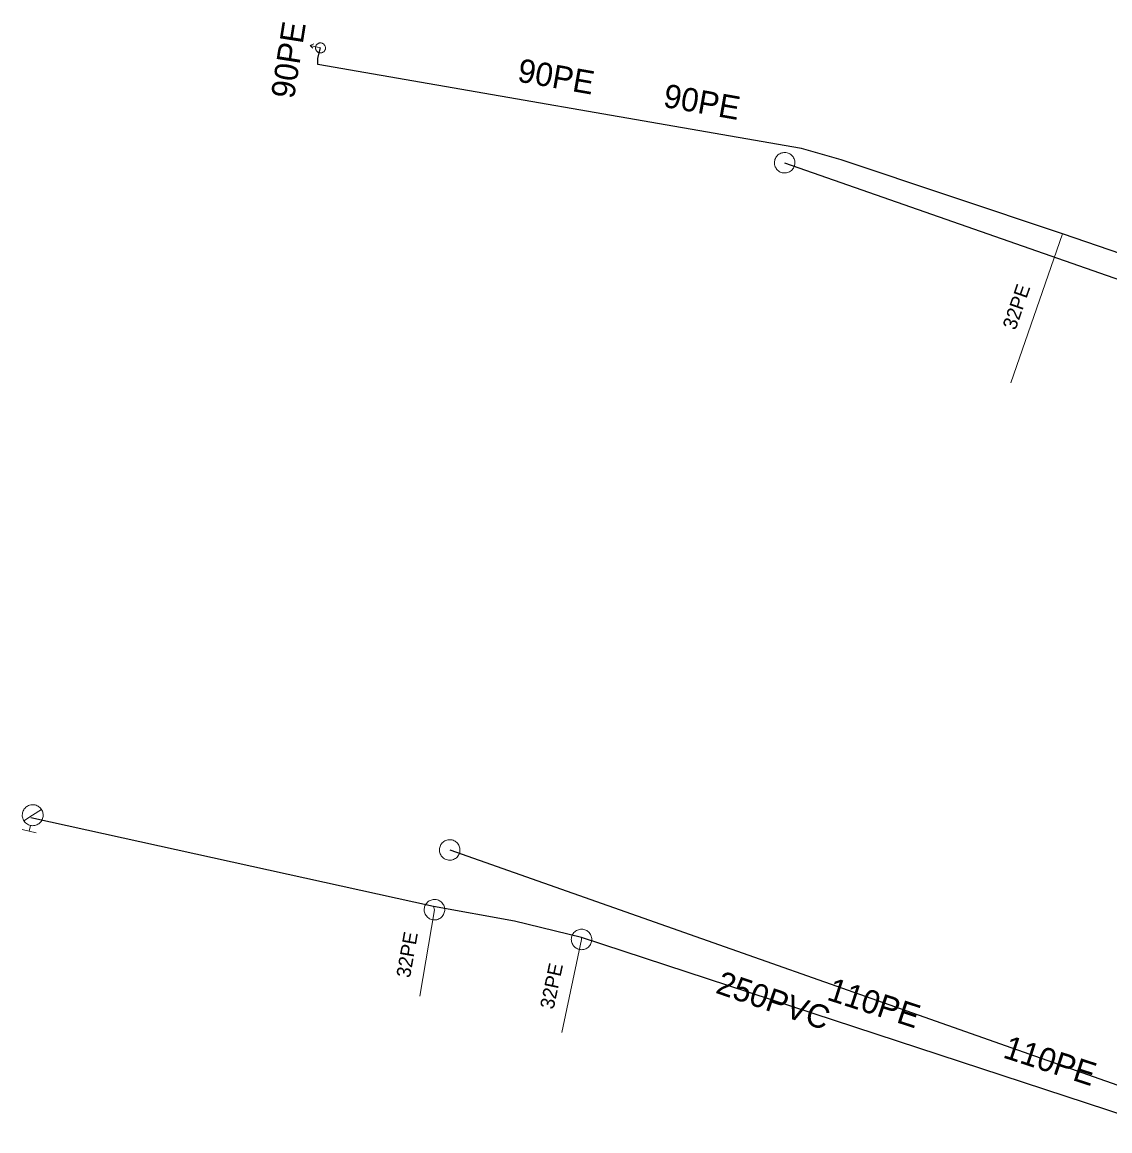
# Model space of a CAD drawing. Extents: x -741806 to -738704, y -1059275 to -1055387.
# Drawn here: x -740744.78 to -740698.33, y -1058174.38 to -1058127.05 of the extents above; entities that cross this region are included whole.
import ezdxf

# ---------------------------------------------------------------- set-up
doc = ezdxf.new("R2010")
doc.units = 0
doc.header["$LTSCALE"] = 0.4
for name, color, linetype, lineweight in [('2', 7, 'Continuous', 25), ('21', 7, 'Continuous', 13), ('3', 7, 'Continuous', 13), ('36', 7, 'Continuous', 13), ('50', 7, 'Continuous', 13), ('51', 7, 'Continuous', 13), ('52', 7, 'Continuous', 25)]:
    doc.layers.add(name, color=color, linetype=linetype, lineweight=lineweight)
for name, color, linetype in [('5', 7, 'Continuous'), ('53', 7, 'Continuous'), ('54', 7, 'Continuous')]:
    doc.layers.add(name, color=color, linetype=linetype)

msp = doc.modelspace()

# ---------------------------------------------------------------- linework, layer by layer
at = {"layer": '2'}
for p, q in [((-740712.219, -1058133.05), (-740673.62, -1058146.55)), ((-740726.52, -1058162.389), (-740696.93, -1058172.81))]:
    msp.add_line(p, q, dxfattribs=at)
at = {"layer": '21'}
msp.add_line((-740700.35, -1058136.09), (-740702.561, -1058142.45), dxfattribs=at)
for points in [[(-740727.219, -1058164.8), (-740727.17, -1058164.94), (-740727.796, -1058168.629)], [(-740720.899, -1058166.12), (-740720.89, -1058166.21), (-740721.732, -1058170.186)]]:
    msp.add_lwpolyline(points, dxfattribs=at)
at = {"layer": '3'}
for points in [[(-740711.805, -1058133.195), (-740711.793, -1058133.151), (-740711.785, -1058133.106), (-740711.781, -1058133.06), (-740711.783, -1058133.015), (-740711.789, -1058132.969), (-740711.8, -1058132.924), (-740711.815, -1058132.882), (-740711.835, -1058132.84), (-740711.86, -1058132.802), (-740711.887, -1058132.765), (-740711.919, -1058132.732), (-740711.954, -1058132.702), (-740711.992, -1058132.677), (-740712.032, -1058132.655), (-740712.074, -1058132.637), (-740712.118, -1058132.624), (-740712.164, -1058132.617), (-740712.209, -1058132.613), (-740712.255, -1058132.615), (-740712.301, -1058132.621), (-740712.345, -1058132.632), (-740712.387, -1058132.647), (-740712.429, -1058132.667), (-740712.468, -1058132.691), (-740712.504, -1058132.719), (-740712.537, -1058132.751), (-740712.567, -1058132.785), (-740712.593, -1058132.824), (-740712.614, -1058132.864), (-740712.631, -1058132.907), (-740712.644, -1058132.95), (-740712.653, -1058132.995), (-740712.656, -1058133.041), (-740712.654, -1058133.087), (-740712.649, -1058133.132), (-740712.638, -1058133.177), (-740712.622, -1058133.219), (-740712.602, -1058133.261), (-740712.578, -1058133.299), (-740712.551, -1058133.335), (-740712.519, -1058133.369), (-740712.484, -1058133.399), (-740712.446, -1058133.425), (-740712.406, -1058133.446), (-740712.363, -1058133.463), (-740712.319, -1058133.477), (-740712.274, -1058133.485), (-740712.229, -1058133.488), (-740712.183, -1058133.486), (-740712.137, -1058133.48), (-740712.093, -1058133.469), (-740712.05, -1058133.454), (-740712.009, -1058133.434), (-740711.97, -1058133.41), (-740711.933, -1058133.382), (-740711.9, -1058133.35), (-740711.871, -1058133.316), (-740711.845, -1058133.277), (-740711.823, -1058133.237), (-740711.806, -1058133.196)], [(-740726.107, -1058162.534), (-740726.094, -1058162.491), (-740726.086, -1058162.446), (-740726.082, -1058162.4), (-740726.084, -1058162.355), (-740726.09, -1058162.309), (-740726.1, -1058162.264), (-740726.116, -1058162.221), (-740726.135, -1058162.18), (-740726.16, -1058162.141), (-740726.188, -1058162.105), (-740726.219, -1058162.072), (-740726.254, -1058162.041), (-740726.292, -1058162.016), (-740726.332, -1058161.994), (-740726.375, -1058161.977), (-740726.419, -1058161.963), (-740726.464, -1058161.956), (-740726.509, -1058161.952), (-740726.555, -1058161.954), (-740726.601, -1058161.96), (-740726.645, -1058161.971), (-740726.687, -1058161.985), (-740726.729, -1058162.006), (-740726.768, -1058162.029), (-740726.805, -1058162.057), (-740726.837, -1058162.089), (-740726.867, -1058162.123), (-740726.893, -1058162.162), (-740726.915, -1058162.202), (-740726.932, -1058162.245), (-740726.945, -1058162.288), (-740726.954, -1058162.333), (-740726.957, -1058162.379), (-740726.955, -1058162.425), (-740726.95, -1058162.47), (-740726.939, -1058162.515), (-740726.924, -1058162.557), (-740726.903, -1058162.599), (-740726.88, -1058162.638), (-740726.852, -1058162.674), (-740726.82, -1058162.707), (-740726.786, -1058162.737), (-740726.748, -1058162.763), (-740726.708, -1058162.785), (-740726.665, -1058162.802), (-740726.621, -1058162.815), (-740726.576, -1058162.824), (-740726.531, -1058162.827), (-740726.485, -1058162.825), (-740726.439, -1058162.819), (-740726.395, -1058162.808), (-740726.352, -1058162.794), (-740726.31, -1058162.773), (-740726.271, -1058162.75), (-740726.235, -1058162.721), (-740726.201, -1058162.69), (-740726.172, -1058162.655), (-740726.146, -1058162.617), (-740726.125, -1058162.577), (-740726.107, -1058162.535)]]:
    msp.add_lwpolyline(points, dxfattribs=at)
at = {"layer": '36'}
msp.add_line((-740732.473, -1058128.04), (-740732.321, -1058127.978), dxfattribs=at)
msp.add_lwpolyline([(-740732.038, -1058128.149), (-740732.473, -1058128.04), (-740732.368, -1058128.166)], dxfattribs=at)
msp.add_lwpolyline([(-740731.986, -1058127.942), (-740732.009, -1058127.937), (-740732.03, -1058127.935), (-740732.053, -1058127.936), (-740732.075, -1058127.938), (-740732.097, -1058127.943), (-740732.117, -1058127.95), (-740732.138, -1058127.96), (-740732.158, -1058127.971), (-740732.176, -1058127.985), (-740732.192, -1058128), (-740732.206, -1058128.017), (-740732.219, -1058128.035), (-740732.23, -1058128.054), (-740732.238, -1058128.075), (-740732.245, -1058128.097), (-740732.249, -1058128.119), (-740732.251, -1058128.141), (-740732.251, -1058128.163), (-740732.248, -1058128.185), (-740732.243, -1058128.207), (-740732.236, -1058128.228), (-740732.227, -1058128.248), (-740732.215, -1058128.267), (-740732.201, -1058128.285), (-740732.186, -1058128.301), (-740732.169, -1058128.316), (-740732.151, -1058128.329), (-740732.131, -1058128.34), (-740732.112, -1058128.349), (-740732.09, -1058128.355), (-740732.068, -1058128.36), (-740732.046, -1058128.361), (-740732.023, -1058128.361), (-740732.002, -1058128.358), (-740731.98, -1058128.353), (-740731.958, -1058128.346), (-740731.939, -1058128.336), (-740731.919, -1058128.325), (-740731.901, -1058128.312), (-740731.885, -1058128.296), (-740731.871, -1058128.279), (-740731.858, -1058128.262), (-740731.847, -1058128.242), (-740731.838, -1058128.221), (-740731.831, -1058128.2), (-740731.827, -1058128.178), (-740731.825, -1058128.155), (-740731.826, -1058128.134), (-740731.829, -1058128.111), (-740731.834, -1058128.089), (-740731.841, -1058128.069), (-740731.85, -1058128.048), (-740731.862, -1058128.029), (-740731.875, -1058128.011), (-740731.89, -1058127.995), (-740731.907, -1058127.98), (-740731.925, -1058127.968), (-740731.945, -1058127.957), (-740731.965, -1058127.948)], close=True, dxfattribs=at)
at = {"layer": '50'}
for p, q in [((-740744.328, -1058160.904), (-740743.95, -1058160.663)), ((-740744.328, -1058160.904), (-740744.702, -1058161.141)), ((-740744.776, -1058161.52), (-740744.476, -1058161.586)), ((-740744.423, -1058161.341), (-740744.476, -1058161.586)), ((-740744.176, -1058161.652), (-740744.476, -1058161.586))]:
    msp.add_line(p, q, dxfattribs=at)
msp.add_lwpolyline([(-740744.76, -1058160.805), (-740744.768, -1058160.853), (-740744.773, -1058160.899), (-740744.77, -1058160.947), (-740744.763, -1058160.993), (-740744.753, -1058161.036), (-740744.735, -1058161.082), (-740744.714, -1058161.122), (-740744.69, -1058161.163), (-740744.662, -1058161.2), (-740744.628, -1058161.232), (-740744.593, -1058161.263), (-740744.555, -1058161.29), (-740744.512, -1058161.31), (-740744.469, -1058161.328), (-740744.425, -1058161.34), (-740744.379, -1058161.347), (-740744.334, -1058161.352), (-740744.286, -1058161.349), (-740744.24, -1058161.342), (-740744.193, -1058161.331), (-740744.151, -1058161.315), (-740744.108, -1058161.294), (-740744.069, -1058161.269), (-740744.033, -1058161.241), (-740743.998, -1058161.208), (-740743.968, -1058161.173), (-740743.943, -1058161.134), (-740743.919, -1058161.092), (-740743.905, -1058161.048), (-740743.889, -1058161.005), (-740743.882, -1058160.957), (-740743.879, -1058160.91), (-740743.881, -1058160.866), (-740743.887, -1058160.818), (-740743.899, -1058160.773), (-740743.914, -1058160.729), (-740743.936, -1058160.688), (-740743.96, -1058160.647), (-740743.99, -1058160.61), (-740744.022, -1058160.578), (-740744.06, -1058160.547), (-740744.098, -1058160.522), (-740744.137, -1058160.5), (-740744.183, -1058160.481), (-740744.228, -1058160.468), (-740744.273, -1058160.461), (-740744.32, -1058160.459), (-740744.367, -1058160.46), (-740744.413, -1058160.467), (-740744.459, -1058160.479), (-740744.502, -1058160.494), (-740744.545, -1058160.515), (-740744.583, -1058160.54), (-740744.62, -1058160.567), (-740744.652, -1058160.602), (-740744.684, -1058160.636), (-740744.71, -1058160.676), (-740744.73, -1058160.717), (-740744.748, -1058160.761)], close=True, dxfattribs=at)
at = {"layer": '51'}
for points in [[(-740727.023, -1058165.351), (-740726.981, -1058165.334), (-740726.941, -1058165.312), (-740726.903, -1058165.286), (-740726.869, -1058165.257), (-740726.837, -1058165.223), (-740726.809, -1058165.187), (-740726.786, -1058165.148), (-740726.765, -1058165.106), (-740726.751, -1058165.063), (-740726.74, -1058165.019), (-740726.734, -1058164.973), (-740726.733, -1058164.927), (-740726.736, -1058164.881), (-740726.745, -1058164.837), (-740726.758, -1058164.793), (-740726.776, -1058164.75), (-740726.798, -1058164.71), (-740726.824, -1058164.673), (-740726.854, -1058164.638), (-740726.888, -1058164.606), (-740726.924, -1058164.579), (-740726.962, -1058164.554), (-740727.004, -1058164.535), (-740727.047, -1058164.52), (-740727.092, -1058164.509), (-740727.138, -1058164.503), (-740727.183, -1058164.502), (-740727.229, -1058164.506), (-740727.274, -1058164.515), (-740727.318, -1058164.528), (-740727.36, -1058164.545), (-740727.4, -1058164.567), (-740727.438, -1058164.594), (-740727.472, -1058164.623), (-740727.504, -1058164.656), (-740727.532, -1058164.693), (-740727.555, -1058164.732), (-740727.576, -1058164.773), (-740727.59, -1058164.817), (-740727.601, -1058164.861), (-740727.607, -1058164.907), (-740727.608, -1058164.953), (-740727.604, -1058164.998), (-740727.596, -1058165.043), (-740727.582, -1058165.087), (-740727.565, -1058165.13), (-740727.542, -1058165.169), (-740727.517, -1058165.207), (-740727.487, -1058165.242), (-740727.453, -1058165.273), (-740727.417, -1058165.301), (-740727.378, -1058165.325), (-740727.337, -1058165.344), (-740727.294, -1058165.36), (-740727.249, -1058165.37), (-740727.203, -1058165.376), (-740727.158, -1058165.377), (-740727.112, -1058165.373), (-740727.067, -1058165.365), (-740727.024, -1058165.352)], [(-740721.305, -1058166.073), (-740721.317, -1058166.116), (-740721.324, -1058166.161), (-740721.327, -1058166.208), (-740721.325, -1058166.252), (-740721.317, -1058166.298), (-740721.306, -1058166.343), (-740721.289, -1058166.385), (-740721.269, -1058166.426), (-740721.244, -1058166.464), (-740721.215, -1058166.5), (-740721.183, -1058166.533), (-740721.147, -1058166.562), (-740721.109, -1058166.587), (-740721.069, -1058166.608), (-740721.026, -1058166.624), (-740720.981, -1058166.637), (-740720.936, -1058166.644), (-740720.891, -1058166.646), (-740720.845, -1058166.644), (-740720.799, -1058166.636), (-740720.755, -1058166.625), (-740720.712, -1058166.609), (-740720.672, -1058166.588), (-740720.633, -1058166.564), (-740720.597, -1058166.534), (-740720.564, -1058166.502), (-740720.536, -1058166.467), (-740720.511, -1058166.428), (-740720.49, -1058166.387), (-740720.473, -1058166.345), (-740720.462, -1058166.301), (-740720.454, -1058166.256), (-740720.452, -1058166.21), (-740720.454, -1058166.165), (-740720.461, -1058166.119), (-740720.473, -1058166.074), (-740720.489, -1058166.032), (-740720.509, -1058165.991), (-740720.535, -1058165.953), (-740720.563, -1058165.917), (-740720.595, -1058165.884), (-740720.631, -1058165.855), (-740720.669, -1058165.831), (-740720.71, -1058165.809), (-740720.753, -1058165.793), (-740720.797, -1058165.78), (-740720.842, -1058165.774), (-740720.888, -1058165.771), (-740720.934, -1058165.773), (-740720.979, -1058165.781), (-740721.023, -1058165.793), (-740721.066, -1058165.808), (-740721.107, -1058165.829), (-740721.145, -1058165.854), (-740721.181, -1058165.883), (-740721.214, -1058165.915), (-740721.242, -1058165.95), (-740721.268, -1058165.989), (-740721.288, -1058166.03), (-740721.304, -1058166.072)]]:
    msp.add_lwpolyline(points, dxfattribs=at)
at = {"layer": '52'}
for points in [[(-740732.149, -1058128.85), (-740732.149, -1058128.59), (-740732.039, -1058128.149)], [(-740679.969, -1058143.04), (-740680.219, -1058142.919), (-740692.92, -1058138.57), (-740696.82, -1058137.3), (-740700.35, -1058136.09), (-740709.8, -1058132.929), (-740711.5, -1058132.44), (-740732.149, -1058128.85)], [(-740695.73, -1058174.379), (-740720.899, -1058166.12), (-740723.75, -1058165.429), (-740727.219, -1058164.8), (-740744.41, -1058161.02)]]:
    msp.add_lwpolyline(points, dxfattribs=at)

# ---------------------------------------------------------------- texts
at = {"layer": '5'}
msp.add_text('250PVC', height=1, rotation=341, dxfattribs=at).set_placement((-740715.213, -1058168.475))
at = {"layer": '53'}
for s, rotation, p in [('90PE', 81, (-740733.171, -1058130.354)), ('90PE', 350, (-740723.669, -1058129.577)), ('90PE', 350, (-740717.444, -1058130.66)), ('110PE ', 342, (-740710.46, -1058168.771)), ('110PE ', 342, (-740702.941, -1058171.238))]:
    msp.add_text(s, height=1, rotation=rotation, dxfattribs=at).set_placement(p)
at = {"layer": '54'}
for rotation, p in [(71, (-740702.36, -1058140.224)), (80, (-740728.216, -1058167.876)), (78, (-740722.086, -1058169.219))]:
    msp.add_text('32PE', height=0.6, rotation=rotation, dxfattribs=at).set_placement(p)

doc.saveas('drawing.dxf')
